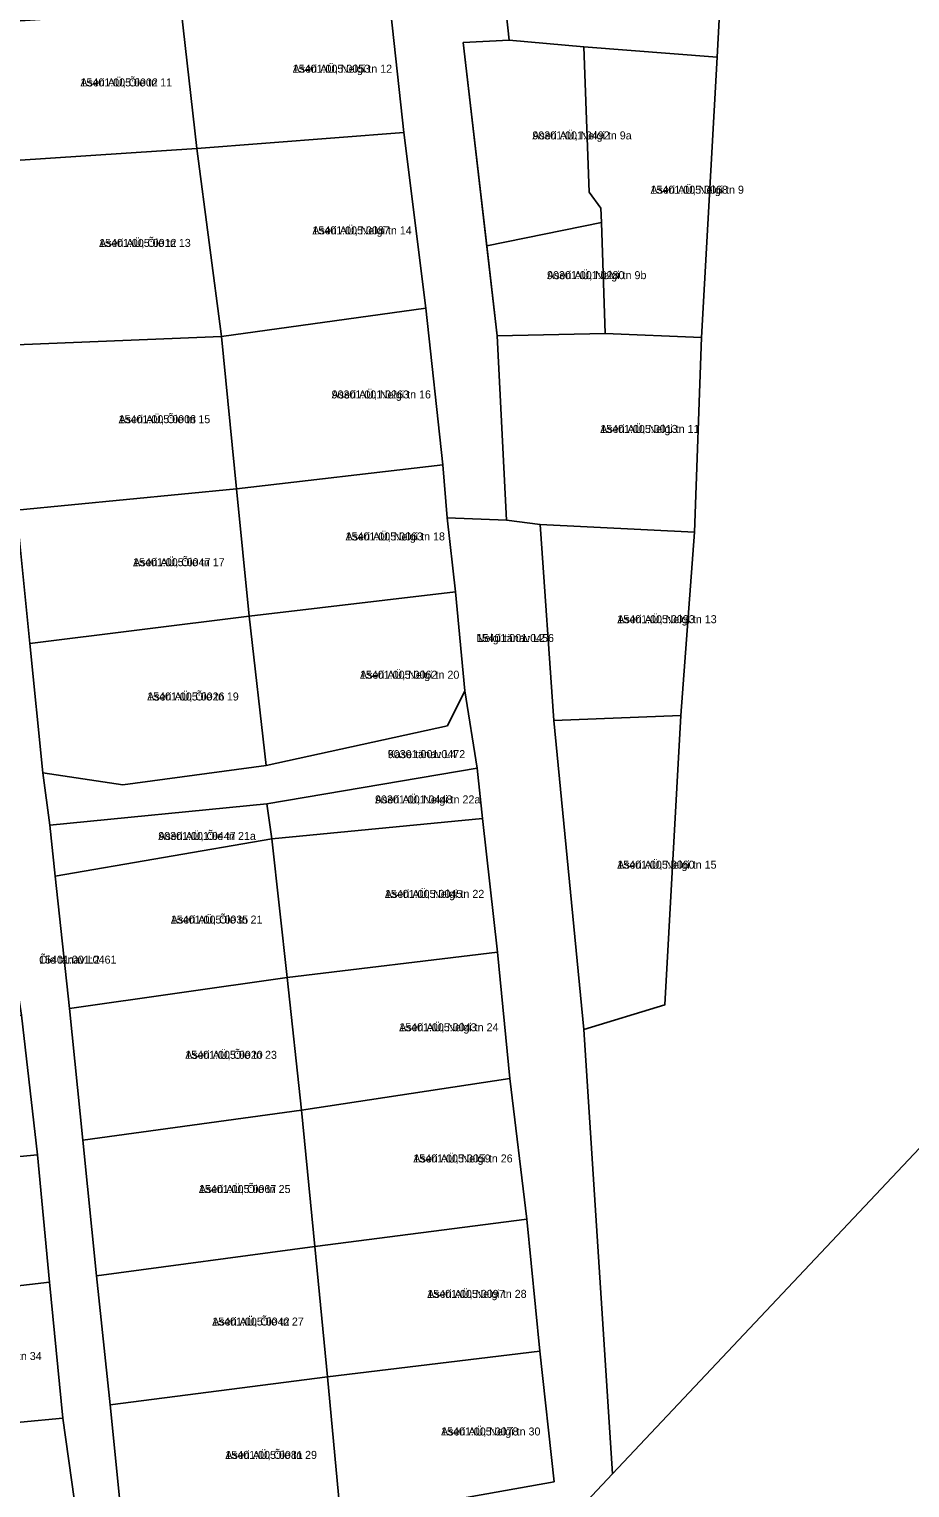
# Model space of a CAD drawing. Extents: x 634518 to 667988, y 6584667 to 6604739.
# Drawn here: x 663487.1 to 663652.2, y 6593164.3 to 6593437.7 of the extents above; entities that cross this region are included whole.
import ezdxf

# ---------------------------------------------------------------- set-up
doc = ezdxf.new("R2010")
doc.units = 0
for name, color, linetype in [('L_AADRESS', 7, 'Continuous'), ('PIIR', 7, 'Continuous'), ('TUNNUS', 7, 'Continuous')]:
    doc.layers.add(name, color=color, linetype=linetype)

msp = doc.modelspace()

# ---------------------------------------------------------------- linework, layer by layer
at = {"layer": 'PIIR'}
for points in [[(663941.55, 6593409.89), (663688.91, 6593264.97), (663596.43, 6593166.89), (663591.11, 6593250.17), (663606.28, 6593254.84), (663609.26, 6593309.01), (663611.82, 6593343.38), (663613.16, 6593379.91), (663616.05, 6593432.42), (663617.41, 6593457.15), (663617.88, 6593482.53), (663617.41, 6593509.26), (663616.87, 6593531.5), (663645.18, 6593514.66), (663663.37, 6593546.3), (663682.17, 6593578.9), (663679.83, 6593616.01), (663675.98, 6593658.01), (663673.35, 6593686.65)], [(663497.75, 6593146.66), (663493.44, 6593177.36), (663490.91, 6593202.86), (663488.67, 6593226.67), (663485.68, 6593252.87), (663481.81, 6593278.04), (663480.5, 6593287.65), (663478.94, 6593299.1), (663476.85, 6593330.09), (663474.54, 6593352.15), (663473.37, 6593377.76), (663481.51, 6593378.39), (663484.73, 6593347.53), (663487.23, 6593322.53), (663489.7, 6593298.29), (663491.02, 6593288.46), (663492.03, 6593278.94), (663494.68, 6593254.15), (663497.19, 6593229.42), (663499.76, 6593204.01), (663502.29, 6593179.87), (663504.87, 6593154.31)]]:
    msp.add_lwpolyline(points, dxfattribs=at)
for points in [[(663542.98, 6593575.88), (663557.06, 6593567.44), (663557.24, 6593562.6), (663560.98, 6593504.78), (663565.18, 6593483.24), (663566.79, 6593461.61), (663574.1, 6593461.69), (663574.6, 6593458.74), (663577.09, 6593435.63), (663568.49, 6593435.15), (663574.87, 6593380.22), (663576.61, 6593345.66), (663565.44, 6593346.11), (663564.64, 6593356.03), (663561.5, 6593385.4), (663557.33, 6593418.31), (663554.59, 6593443.7), (663552.41, 6593467.38), (663550.46, 6593493.47), (663548.86, 6593517.55), (663545.9, 6593543.8), (663543.51, 6593568.74)], [(663577.09, 6593435.63), (663574.6, 6593458.74), (663617.41, 6593457.15), (663616.05, 6593432.42), (663591.11, 6593434.34)], [(663554.59, 6593443.7), (663557.33, 6593418.31), (663518.55, 6593415.33), (663515.6, 6593441.25)], [(663515.6, 6593441.25), (663518.55, 6593415.33), (663477.8, 6593412.62), (663474.98, 6593438.56)], [(663591.11, 6593434.34), (663592.1, 6593407.13), (663594.27, 6593404.12), (663594.37, 6593401.43), (663572.92, 6593397.04), (663568.49, 6593435.15), (663577.09, 6593435.63)], [(663595.11, 6593380.62), (663594.37, 6593401.43), (663594.27, 6593404.12), (663592.1, 6593407.13), (663591.11, 6593434.34), (663616.05, 6593432.42), (663613.16, 6593379.91)], [(663523.16, 6593380.1), (663518.55, 6593415.33), (663557.33, 6593418.31), (663561.5, 6593385.4)], [(663518.55, 6593415.33), (663523.16, 6593380.1), (663481.51, 6593378.39), (663477.8, 6593412.62)], [(663595.11, 6593380.62), (663574.87, 6593380.22), (663572.92, 6593397.04), (663594.37, 6593401.43)], [(663564.64, 6593356.03), (663525.97, 6593351.51), (663523.16, 6593380.1), (663561.5, 6593385.4)], [(663523.16, 6593380.1), (663525.97, 6593351.51), (663484.73, 6593347.53), (663481.51, 6593378.39)], [(663582.91, 6593344.83), (663576.61, 6593345.66), (663574.87, 6593380.22), (663595.11, 6593380.62), (663613.16, 6593379.91), (663611.82, 6593343.38)], [(663528.36, 6593327.67), (663525.97, 6593351.51), (663564.64, 6593356.03), (663565.44, 6593346.11), (663567, 6593332.22)], [(663525.97, 6593351.51), (663528.36, 6593327.67), (663487.23, 6593322.53), (663484.73, 6593347.53)], [(663565.44, 6593346.11), (663576.61, 6593345.66), (663582.91, 6593344.83), (663585.43, 6593308.12), (663591.11, 6593250.17), (663596.43, 6593166.89), (663586.76, 6593156.63), (663546.5, 6593150.83), (663545.54, 6593158.28), (663585.52, 6593165.42), (663582.85, 6593189.91), (663580.38, 6593214.67), (663577.24, 6593241), (663574.9, 6593264.66), (663572.1, 6593289.75), (663571.07, 6593299.19), (663568.79, 6593313.64), (663567, 6593332.22)], [(663582.91, 6593344.83), (663611.82, 6593343.38), (663609.26, 6593309.01), (663585.43, 6593308.12)], [(663531.54, 6593299.65), (663528.36, 6593327.67), (663567, 6593332.22), (663568.79, 6593313.64), (663565.53, 6593307.12)], [(663504.71, 6593296.03), (663489.7, 6593298.29), (663487.23, 6593322.53), (663528.36, 6593327.67), (663531.54, 6593299.65)], [(663568.79, 6593313.64), (663571.07, 6593299.19), (663531.7, 6593292.49), (663491.02, 6593288.46), (663489.7, 6593298.29), (663504.71, 6593296.03), (663531.54, 6593299.65), (663565.53, 6593307.12)], [(663606.28, 6593254.84), (663591.11, 6593250.17), (663585.43, 6593308.12), (663609.26, 6593309.01)], [(663571.07, 6593299.19), (663572.1, 6593289.75), (663532.59, 6593285.93), (663531.7, 6593292.49)], [(663491.02, 6593288.46), (663531.7, 6593292.49), (663532.59, 6593285.93), (663492.03, 6593278.94)], [(663574.9, 6593264.66), (663535.5, 6593259.96), (663532.59, 6593285.93), (663572.1, 6593289.75)], [(663535.5, 6593259.96), (663494.68, 6593254.15), (663492.03, 6593278.94), (663532.59, 6593285.93)], [(663417.18, 6593140.75), (663456.2, 6593143.61), (663497.75, 6593146.66), (663523.06, 6593148.51), (663523.47, 6593136.28), (663526.25, 6593052.89), (663624.97, 6593056.18), (663645.86, 6593114.27), (663586.76, 6593156.63), (663596.43, 6593166.89), (663688.91, 6593264.97), (663768.37, 6593098.64), (663666.98, 6593099.13), (663580.25, 6592857.99), (663615.7, 6592838.09), (663607.46, 6592739.74), (663604.16, 6592694.68), (663491.37, 6592703.11), (663392.51, 6592710.65), (663429.67, 6592795.74), (663425.58, 6592915.6), (663417.84, 6593115.56)], [(663574.9, 6593264.66), (663577.24, 6593241), (663538.16, 6593235.06), (663535.5, 6593259.96)], [(663535.5, 6593259.96), (663538.16, 6593235.06), (663497.19, 6593229.42), (663494.68, 6593254.15)], [(663488.67, 6593226.67), (663448.93, 6593222.93), (663446.23, 6593249.06), (663485.68, 6593252.87)], [(663538.16, 6593235.06), (663577.24, 6593241), (663580.38, 6593214.67), (663540.67, 6593209.53)], [(663499.76, 6593204.01), (663497.19, 6593229.42), (663538.16, 6593235.06), (663540.67, 6593209.53)], [(663488.67, 6593226.67), (663490.91, 6593202.86), (663451.26, 6593198.23), (663448.93, 6593222.93)], [(663540.67, 6593209.53), (663580.38, 6593214.67), (663582.85, 6593189.91), (663543.07, 6593185.11)], [(663540.67, 6593209.53), (663543.07, 6593185.11), (663502.29, 6593179.87), (663499.76, 6593204.01)], [(663451.26, 6593198.23), (663490.91, 6593202.86), (663493.44, 6593177.36), (663453.7, 6593173.62)], [(663545.54, 6593158.28), (663543.07, 6593185.11), (663582.85, 6593189.91), (663585.52, 6593165.42)], [(663504.87, 6593154.31), (663502.29, 6593179.87), (663543.07, 6593185.11), (663545.54, 6593158.28)], [(663456.2, 6593143.61), (663455.75, 6593149.21), (663453.7, 6593173.62), (663493.44, 6593177.36), (663497.75, 6593146.66)]]:
    msp.add_lwpolyline(points, close=True, dxfattribs=at)

# ---------------------------------------------------------------- texts
at = {"layer": 'L_AADRESS'}
for s, p in [('Aseri AÜ, Õie tn 11', (663496.74, 6593426.94)), ('Aseri AÜ, Nelgi tn 12', (663536.53, 6593429.51)), ('Aseri AÜ, Nelgi tn 9a', (663581.43, 6593417.01)), ('Aseri AÜ, Nelgi tn 9', (663603.58, 6593406.83)), ('Aseri AÜ, Õie tn 13', (663500.24, 6593396.86)), ('Aseri AÜ, Nelgi tn 14', (663540.21, 6593399.21)), ('Aseri AÜ, Nelgi tn 9b', (663584.19, 6593390.82)), ('Aseri AÜ, Nelgi tn 16', (663543.81, 6593368.46)), ('Aseri AÜ, Õie tn 15', (663503.9, 6593363.82)), ('Aseri AÜ, Nelgi tn 11', (663594.15, 6593362)), ('Aseri AÜ, Nelgi tn 18', (663546.43, 6593341.85)), ('Aseri AÜ, Õie tn 17', (663506.6, 6593337.02)), ('Aseri AÜ, Nelgi tn 13', (663597.36, 6593326.34)), ('Nelgi tänav L2', (663570.98, 6593322.81)), ('Aseri AÜ, Nelgi tn 20', (663549.13, 6593315.93)), ('Aseri AÜ, Õie tn 19', (663509.24, 6593311.85)), ('Kase tänav L4', (663554.34, 6593301.05)), ('Aseri AÜ, Nelgi tn 22a', (663551.95, 6593292.56)), ('Aseri AÜ, Õie tn 21a', (663511.33, 6593285.71)), ('Aseri AÜ, Nelgi tn 15', (663597.34, 6593280.33)), ('Aseri AÜ, Nelgi tn 22', (663553.8, 6593274.86)), ('Aseri AÜ, Õie tn 21', (663513.68, 6593270.04)), ('Õie tänav L2', (663488.99, 6593262.53)), ('Aseri AÜ, Nelgi tn 24', (663556.47, 6593249.86)), ('Aseri AÜ, Õie tn 23', (663516.39, 6593244.69)), ('Aseri AÜ, Nelgi tn 26', (663559.12, 6593225.27)), ('Aseri AÜ, Õie tn 25', (663518.94, 6593219.54)), ('Aseri AÜ, Nelgi tn 28', (663561.74, 6593199.89)), ('Aseri AÜ, Õie tn 27', (663521.43, 6593194.7)), ('Aseri AÜ, Õie tn 34', (663472.31, 6593188.24)), ('Aseri AÜ, Nelgi tn 30', (663564.33, 6593174.1)), ('Aseri AÜ, Õie tn 29', (663523.9, 6593169.71))]:
    msp.add_text(s, height=1.5, dxfattribs=at).set_placement(p)
at = {"layer": 'TUNNUS'}
for s, p in [('15401:005:0053', (663536.53, 6593429.51)), ('15401:005:0002', (663496.74, 6593426.94)), ('90301:001:0492', (663581.43, 6593417.01)), ('15401:005:0068', (663603.58, 6593406.83)), ('15401:005:0087', (663540.21, 6593399.21)), ('15401:005:0012', (663500.24, 6593396.86)), ('90301:001:0280', (663584.19, 6593390.82)), ('90301:001:0263', (663543.81, 6593368.46)), ('15401:005:0008', (663503.9, 6593363.82)), ('15401:005:0013', (663594.15, 6593362)), ('15401:005:0063', (663546.43, 6593341.85)), ('15401:005:0047', (663506.6, 6593337.02)), ('15401:005:0093', (663597.36, 6593326.34)), ('15401:001:0456', (663570.98, 6593322.81)), ('15401:005:0062', (663549.13, 6593315.93)), ('15401:005:0026', (663509.24, 6593311.85)), ('90301:001:0472', (663554.34, 6593301.05)), ('90301:001:0448', (663551.95, 6593292.56)), ('90301:001:0447', (663511.33, 6593285.71)), ('15401:005:0060', (663597.34, 6593280.33)), ('15401:005:0045', (663553.8, 6593274.86)), ('15401:005:0035', (663513.68, 6593270.04)), ('15401:001:0461', (663488.99, 6593262.53)), ('15401:005:0043', (663556.47, 6593249.86)), ('15401:005:0020', (663516.39, 6593244.69)), ('15401:005:0059', (663559.12, 6593225.27)), ('15401:005:0067', (663518.94, 6593219.54)), ('15401:005:0097', (663561.74, 6593199.89)), ('15401:005:0042', (663521.43, 6593194.7)), ('15401:005:0078', (663564.33, 6593174.1)), ('15401:005:0081', (663523.9, 6593169.71))]:
    msp.add_text(s, height=1.5, dxfattribs=at).set_placement(p)

doc.saveas('drawing.dxf')
